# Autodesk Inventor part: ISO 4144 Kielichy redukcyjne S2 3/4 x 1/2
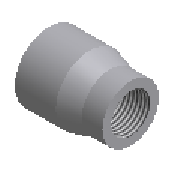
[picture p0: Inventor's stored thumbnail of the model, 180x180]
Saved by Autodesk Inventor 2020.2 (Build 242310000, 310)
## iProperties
Manager: www.cadconsulting.pl
Company: Fabian Stasiak CAD Consulting
NAME: PIPING: ISO 4144 Reducing Socket M2
DATA: <meta><inlinegroups number="1" deflen="3.9"></inlinegroups><connections number="2"></connections><angles><a>3.14159265358979</a></angles></meta>
IsCustomPart: 0
Created: 2014-02
Part Number: ISO 4144 Kielichy redukcyjne S2 3/4 x 1/2
Material: Stal nierdzewna
Description: Rurociągi - Elementy ze stali nierdzewnej gwintowane zgodnie z ISO 7-1 - Kielichy redukcyjne S3
Document SubType Name: Modeling
Standard: ISO 4144
Designer: F.Stasiak
Standard Revision: Second edition 2003-03-15
Standards Organization: ISO
Language: pl-PL
Size Designation: 3/4 x 1/2
Categories: <MemberInstance><Categories><Category DisplayName="Rury cienko- i grubościenne" InternalName="4347fa0f-2144-441d-94cd-e3e15c92b736" Mnemonic="TUBEANDPIPE"><Cate
Density: 1 g/cm^3
Appearance: Częściowo polerowana
Catalog Web Link: www.expertbooks.pl
B1: 14.100 mm
Author: F.Stasiak
Subject: Zbiór ćwiczeń. Autodesk Inventor 2020. Kurs Professional
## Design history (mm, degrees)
sketch "Sketch1"
  geometry: L1 (0, 16.25)-(-19.5, 16.25); L2 (-19.5, 16.25)-(-29.25, 13.5); L3 (-29.25, 13.5)-(-39, 13.5); L4 (-39, 0)-(0, 0); L5 (-39, 0)-(-39, 9.315); L6 (0, 0)-(0, 12.058); L7 (-39, 13.5)-(-39, 9.315); L8 (-39, 9.315)-(-26.3, 8.919); L9 (-26.3, 8.919)-(-16.73, 11.618); L10 (0, 16.25)-(0, 12.058); L11 (-16.73, 11.618)-(-14.1, 11.618); L12 (-14.1, 11.618)-(0, 12.058); L13 (-26.3, 8.919)-(-26.3, 0); L14 (-16.73, 11.618)-(-16.73, 0); L15 (-14.1, 11.618)-(-14.1, 0)
  constraints: 30 end point, 5 parallel, 5 perpendicular, 3 point on line, 1 collinear, 1 vertical, 1 other
  dimensions: "d0" = 32.5 diameter of L1.start L4 (= D1); "d1" = 27 diameter of L3.end L4 (= D2); "d2" = 1.78991 deg angle of L4 L12; "d3" = 1.78991 deg angle of L4 L8; "d4" = 39 distance between parallel lines of L10 L7 (= L); "d5" = 12.7 horizontal distance of L5.end L8.end (= B2); "d6" = 14.1 horizontal distance of L11.end L6.end (= B1); "d7" = 19.5 distance of L1.start L1.end (= 0.5 x L); "d8" = 9.75 distance of L2.end L3.end (= 0.25 x L); "d10" = 24.117 diameter of L6.end L4 (= MD1); "d11" = 18.631 diameter of L5.end L4 (= MD2)
revolve "Revolution1" sketch "Sketch1" stored, may be unused: angle "d9" = 90 deg
workpoint "Work Point5"
workpoint "Work Point8"
workaxis "Work Axis7"
workpoint "Work Point11"
workaxis "Work Axis8"
workpoint "Work Point12"
body "Solid1"
feature "Gwint1" dims "d19" = 25.4, "d20" = 0
feature "Gwint2" dims "d21" = 25.4, "d22" = 0
other parameters: "D1" = 32.5 [user parameter; used in 1 equation term], "D2" = 27 [user parameter; used in 1 equation term], "L" = 39 [user parameter; used in 3 equation terms], "MD1" = 24.117 [user parameter; used in 1 equation term], "MD2" = 18.631 [user parameter; used in 1 equation term], "B1" = 14.1 [user parameter; used in 1 equation term], "B2" = 12.7 [user parameter; used in 1 equation term], "Size_Designation" = 12.345 [user parameter]
